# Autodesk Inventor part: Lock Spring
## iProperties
Created: 2009-03
Part Number: Lock Spring
Document SubType Name: Modeling
Designer: tangg
Density: 7.84 g/cm^3
Material: Steel, High Strength Low Alloy
Mass: 2.03542 g
Surface Area: 8.33252 cm^2
Volume: 0.25962 cm^3
Author: tangg
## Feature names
1. Sweep1
